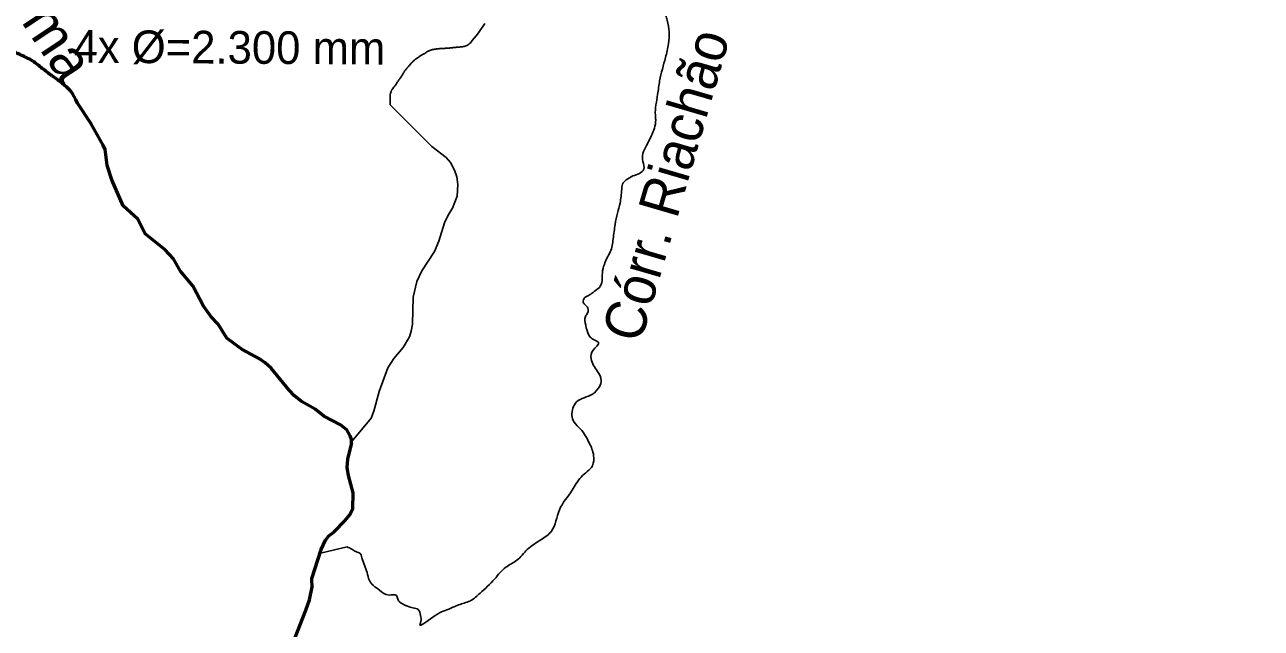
# Model space of a CAD drawing. Extents: x -1643653 to 4543381, y 1624270 to 13878484.
# Drawn here: x 702315 to 717468, y 8942875 to 8950266 of the extents above; entities that cross this region are included whole.
import ezdxf
from ezdxf.enums import TextEntityAlignment as Align

# ---------------------------------------------------------------- set-up
doc = ezdxf.new("R2010")
doc.units = 0
doc.header["$LTSCALE"] = 160
for name, color, linetype, lineweight in [('24', 7, 'Continuous', 25), ('50', 7, 'Continuous', 13), ('60', 7, 'Continuous', 13)]:
    doc.layers.add(name, color=color, linetype=linetype, lineweight=lineweight)
doc.layers.add('49', color=7, linetype='Continuous')

msp = doc.modelspace()

# ---------------------------------------------------------------- linework, layer by layer
at = {"layer": '24'}
msp.add_line((706264.7, 8943870.5), (705937.8, 8943795.8), dxfattribs=at)
for points in [[(707335.3, 8949965.8), (707343.4, 8949967), (707351.5, 8949968.2), (707359.7, 8949969.2), (707368, 8949970.1), (707376.3, 8949971), (707384.6, 8949971.8), (707392.9, 8949972.5), (707401.3, 8949973.2), (707409.7, 8949973.8), (707418.2, 8949974.3), (707426.8, 8949974.9), (707435.5, 8949975.4), (707444.3, 8949975.9), (707453.3, 8949976.5), (707462.4, 8949977), (707471.6, 8949977.5), (707480.8, 8949978.1), (707490.1, 8949978.7), (707499.4, 8949979.3), (707508.7, 8949980.1), (707517.9, 8949980.8), (707527.1, 8949981.7), (707536.2, 8949982.6), (707545.5, 8949983.6), (707554.9, 8949984.6), (707564.5, 8949985.6), (707574.4, 8949986.7), (707584.7, 8949987.8), (707595.5, 8949988.9), (707606.7, 8949990), (707618.3, 8949991.1), (707630.1, 8949992.2), (707642.1, 8949993.3), (707654.1, 8949994.5), (707666, 8949995.7), (707677.6, 8949997), (707688.8, 8949998.3), (707699.6, 8949999.9), (707710.4, 8950002.2), (707721.5, 8950006), (707733.5, 8950012.1), (707746.8, 8950021), (707762, 8950033.6), (707779.3, 8950050.5), (707799.4, 8950072.5), (707822.3, 8950099.8), (707847.6, 8950131.9), (707874.3, 8950167.3), (707901.5, 8950205.1), (707928.3, 8950244.1), (707953.9, 8950283.2)], [(707103, 8949843.3), (707109.6, 8949848.4), (707116.2, 8949853.3), (707122.7, 8949858), (707129.3, 8949862.5), (707136, 8949866.9), (707142.6, 8949871.1), (707149.3, 8949875.3), (707156.1, 8949879.4), (707162.9, 8949883.5), (707169.8, 8949887.6), (707176.7, 8949891.7), (707183.6, 8949895.8), (707190.4, 8949899.8), (707197.1, 8949903.8), (707203.7, 8949907.7), (707210, 8949911.6), (707216.1, 8949915.5), (707222, 8949919.2), (707227.5, 8949922.9), (707233, 8949926.5), (707238.3, 8949930), (707243.6, 8949933.4), (707248.9, 8949936.6), (707254.3, 8949939.8), (707259.8, 8949942.8), (707265.6, 8949945.6), (707271.6, 8949948.3), (707277.8, 8949950.8), (707284.2, 8949953.2), (707290.9, 8949955.5), (707297.8, 8949957.5), (707304.9, 8949959.5), (707312.2, 8949961.3), (707319.7, 8949962.9), (707327.4, 8949964.4), (707335.3, 8949965.8)], [(707005.5, 8949071.8), (706794.5, 8949287.1), (706791.8, 8949336), (706791.8, 8949375.1), (706794.1, 8949406), (706798.3, 8949430), (706803.9, 8949448.5), (706810.8, 8949462.9), (706818.3, 8949474.8), (706826.2, 8949485.3), (706834.1, 8949495.9), (706842, 8949506.5), (706849.7, 8949517.1), (706857.2, 8949527.6), (706864.4, 8949537.9), (706871.4, 8949547.9), (706878, 8949557.5), (706884.2, 8949566.6), (706890, 8949575.2), (706895.4, 8949583.2), (706900.5, 8949590.8), (706905.2, 8949598), (706909.8, 8949604.8), (706914.2, 8949611.4), (706918.5, 8949617.8), (706922.7, 8949624), (706926.9, 8949630.2), (706931, 8949636.2), (706935.2, 8949642.2), (706939.2, 8949648.1), (706943.1, 8949653.8), (706946.9, 8949659.5), (706950.5, 8949665), (706953.9, 8949670.4), (706957.1, 8949675.6), (706960.2, 8949680.7), (706963.2, 8949685.8), (706966.1, 8949690.8), (706969.2, 8949695.8), (706972.4, 8949700.9), (706975.8, 8949706), (706979.6, 8949711.2), (706983.6, 8949716.6), (706988, 8949722.1), (706992.7, 8949727.7), (706997.5, 8949733.4), (707002.5, 8949739.2), (707007.6, 8949745), (707012.8, 8949750.9), (707017.9, 8949756.7), (707023, 8949762.6), (707028, 8949768.5), (707033, 8949774.4), (707038.1, 8949780.3), (707043.2, 8949786.2), (707048.4, 8949792), (707053.8, 8949797.9), (707059.4, 8949803.8), (707065.2, 8949809.7), (707071.2, 8949815.5), (707077.3, 8949821.3), (707083.6, 8949827), (707090, 8949832.6), (707096.5, 8949838.1), (707103, 8949843.3)], [(706318.1, 8945157.8), (706558.5, 8945449.1), (706593.8, 8945534.1), (706659.1, 8945772.7), (706765.2, 8946065.5), (706837, 8946180.3), (706950.8, 8946315.4), (707030.1, 8946442.2), (707051.3, 8946511.7), (707065.5, 8946600.1), (707074.4, 8946928.9), (707120.5, 8947121.8), (707182.7, 8947250.3), (707335.4, 8947487.7), (707390.2, 8947616.9), (707459.2, 8947840.2), (707507, 8947940.8), (707556.4, 8948018.2), (707613.4, 8948168.5), (707621.6, 8948310.7), (707609.1, 8948405.1), (707580.3, 8948486.2), (707531.2, 8948578), (707480.2, 8948638.3), (707302.3, 8948774), (707005.5, 8949071.8)]]:
    msp.add_lwpolyline(points, dxfattribs=at)
at = {"layer": '24', "lineweight": 53}
for points in [[(702375.5, 8949843.3), (702354.4, 8949854.7), (702331.2, 8949866.5), (702306.2, 8949878.5), (702280.1, 8949890.7), (702253.3, 8949902.8), (702226.3, 8949914.8), (702199.6, 8949926.5), (702173.8, 8949937.8), (702149.4, 8949948.6), (702126.7, 8949958.8), (702105.9, 8949968.3), (702086.8, 8949977.3), (702069.4, 8949985.7), (702053.6, 8949993.5), (702039.4, 8950000.7), (702026.7, 8950007.4), (702015.5, 8950013.6), (702005.6, 8950019.3), (701996.8, 8950024.7)], [(702959.4, 8949306.4), (702939.6, 8949349.7), (702920.8, 8949385.8), (702903, 8949415.8), (702886.1, 8949440.6), (702870, 8949461), (702854.7, 8949478), (702839.9, 8949492.5), (702825.7, 8949505.3), (702812, 8949517.4), (702798.5, 8949528.8), (702785.4, 8949539.8), (702772.4, 8949550.3), (702759.4, 8949560.5), (702746.4, 8949570.5), (702733.2, 8949580.3), (702719.8, 8949590.2), (702706.1, 8949600.1), (702692.1, 8949610.1), (702677.8, 8949620.2), (702663.2, 8949630.5), (702648.6, 8949641), (702633.8, 8949651.6), (702618.8, 8949662.5), (702603.9, 8949673.6), (702589, 8949685), (702574.1, 8949696.6), (702559.2, 8949708.4), (702544.4, 8949720.2), (702529.7, 8949732), (702515.2, 8949743.7), (702500.8, 8949755.3), (702486.6, 8949766.7), (702472.5, 8949777.8), (702458.4, 8949788.8), (702443.8, 8949799.6), (702428.6, 8949810.4), (702412.3, 8949821.2), (702394.7, 8949832.2), (702375.5, 8949843.3)], [(705832.8, 8943474.1), (705832.2, 8943483.4), (705948.7, 8943839), (706001.1, 8943954.5), (706040.2, 8944007.2), (706100.5, 8944053.4), (706243.1, 8944196.5), (706294.6, 8944261.8), (706335.3, 8944339.1), (706341.1, 8944535.4), (706282.4, 8944747.1), (706266.1, 8944843.4), (706272.3, 8944945.6), (706319.3, 8945130.2), (706317, 8945185.3), (706304, 8945230.7), (706260.8, 8945306.2), (706182.6, 8945367.1), (705978.7, 8945474.4), (705872.5, 8945557.9), (705704.5, 8945652.5), (705622.4, 8945719.5), (705553.2, 8945790.5), (705334.1, 8946058.7), (705261.1, 8946123.8), (705190.9, 8946173.3), (704977.8, 8946288.6), (704792.6, 8946429), (704685.4, 8946600), (704597.4, 8946688.7), (704507.1, 8946819.4), (704375.5, 8947069.7), (704224.8, 8947248.3), (704136.7, 8947399.1), (704032, 8947515), (703791.7, 8947704), (703699.7, 8947883.2), (703521.3, 8948048.6), (703380.4, 8948367.8), (703323, 8948543.7), (703301.3, 8948739.4), (703276.6, 8948792.4), (703126.8, 8949051.7), (702959.4, 8949306.4)], [(705620.6, 8942742.3), (705760.4, 8943097.5), (705802.3, 8943224.2), (705838.5, 8943384.3), (705832.8, 8943474.1)]]:
    msp.add_lwpolyline(points, dxfattribs=at)
at = {"layer": '24'}
for points in [[(710764.5, 8952700.7), (710808.6, 8952628.5), (710796.5, 8952588.4), (710732.4, 8952468.1), (710692.3, 8952383.8), (710547.9, 8952271.5), (710451.7, 8952187.3), (710375.5, 8952135.1), (710311.4, 8952030.8), (710235.2, 8951906.5), (710171.1, 8951786.1), (710139, 8951641.7), (710082.8, 8951517.4), (709994.7, 8951429.1), (709898.4, 8951365), (709874.4, 8951284.7), (709890.4, 8951220.5), (709970.6, 8951120.3), (709986.6, 8951028), (710018.7, 8950843.5), (710034.7, 8950558.7), (710082.8, 8950490.5), (710167.1, 8950382.2), (710187.1, 8950322), (710211.2, 8950177.6), (710203.1, 8950033.2), (710167.1, 8949864.7), (710094.9, 8949579.9), (710070.8, 8949411.4), (710042.8, 8949159.9), (710046.8, 8949099.7), (710030.7, 8948999.5), (709990.6, 8948903.2), (709934.5, 8948786.9), (709890.4, 8948690.6), (709890.4, 8948590.3), (709902.4, 8948498), (709846.3, 8948445.9), (709766.1, 8948413.8), (709685.9, 8948365.7), (709641.8, 8948313.5), (709629.8, 8948249.3), (709609.8, 8948080.9), (709577.7, 8947960.5), (709549.6, 8947820.1), (709525.6, 8947643.6), (709489.5, 8947483.2), (709449.4, 8947406.9), (709417.3, 8947330.7), (709393.2, 8947226.4), (709385.2, 8947106.1), (709357.2, 8947049.9), (709293, 8946997.8), (709236.9, 8946957.7), (709176.7, 8946925.6)], [(709176.7, 8946925.6), (709156.7, 8946869.4), (709176.7, 8946841.3), (709216.8, 8946793.2), (709212.8, 8946737.1), (709184.8, 8946692.9), (709188.8, 8946588.6), (709228.9, 8946464.3), (709269, 8946420.2), (709348.3, 8946367.6), (709278.6, 8946282.4), (709255.4, 8946174.1), (709332.8, 8946019.3), (709379.2, 8945910.9), (709356, 8945833.6), (709270.9, 8945740.7), (709077.4, 8945647.8), (709031, 8945570.4), (709046.4, 8945400.2), (709123.8, 8945315), (709232.2, 8945144.8), (709286.4, 8944990), (709270.9, 8944866.1), (709131.6, 8944726.8), (709023.2, 8944564.3), (708866.1, 8944324.4), (708770.1, 8944064.3), (708640.1, 8943959.1), (708473, 8943838.3), (708346, 8943708.3), (708209.8, 8943621.6), (708073.6, 8943479.2), (707894, 8943302.8), (707782.6, 8943216.1), (707649.5, 8943166.6), (707510.2, 8943110.8), (707315.1, 8943011.8), (707157.2, 8942922), (707169.6, 8942959.1), (707166.5, 8943030.3), (707135.6, 8943104.6), (707070.6, 8943126.3), (706943.7, 8943172.8), (706884.8, 8943231.6), (706869.3, 8943274.9), (706779.6, 8943281.1), (706661.9, 8943343), (706587.6, 8943398.7), (706538.1, 8943460.7), (706510.2, 8943556.6), (706445.2, 8943739.3), (706423.6, 8943791.9), (706374, 8943813.6), (706321.4, 8943844.5), (706264.7, 8943870.5)]]:
    msp.add_spline(points, degree=3, dxfattribs=at)
at = {"layer": '60', "lineweight": 25}
msp.add_spline([(814781, 9009175.5), (814787.2, 9009173.4), (814796.9, 9009173.4), (814799.4, 9009172.4), (814805.1, 9009174.5), (814805.6, 9009176.5), (814811.7, 9009179.5), (814811.7, 9009179.5), (814801.5, 9009181), (814790.7, 9009181.5), (814784.1, 9009183.1), (814777.4, 9009185.1), (814778.4, 9009175.5)], degree=3, dxfattribs=at)

# ---------------------------------------------------------------- texts
at = {"layer": '49'}
msp.add_text('Rio Ipanema', height=500, rotation=303.53, dxfattribs=at).set_placement((701731.3, 8951111.3), align=Align.CENTER)
at = {"layer": '49', "width": 0.95}
msp.add_text('Córr. Riachão', height=500, rotation=73.734, dxfattribs=at).set_placement((709860.9, 8946353.1))
at = {"layer": '50'}
msp.add_text('4x Ø=2.300 mm', height=400, rotation=359.655, dxfattribs=at).set_placement((704821.7, 8949790), align=Align.CENTER)

doc.saveas('drawing.dxf')
